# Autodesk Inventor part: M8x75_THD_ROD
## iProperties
Shininess: 64.0
Length Units: 11269
Angle Units: 11279
Time Units: 11290
Mass Units: 11283
Length Display Precision: 3
Angle Display Precision: 2
Compacted: True
Part Number: M8x75_THD_ROD
Document SubType Name: Modeling
Created: 2004-08
Material: Stainless Steel, Austenitic
Designer: John Blackburn
Manufacturer: Standard
Standards Organization: Custom
Density: 0.0
Volumn: 0.0
Area: 0.0
PropertySet Name: Model Information
Control State: 0
Master: False
Checked Out: False
Author: John Blackburn
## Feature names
1. Extrusion1
2. Chamfer1
